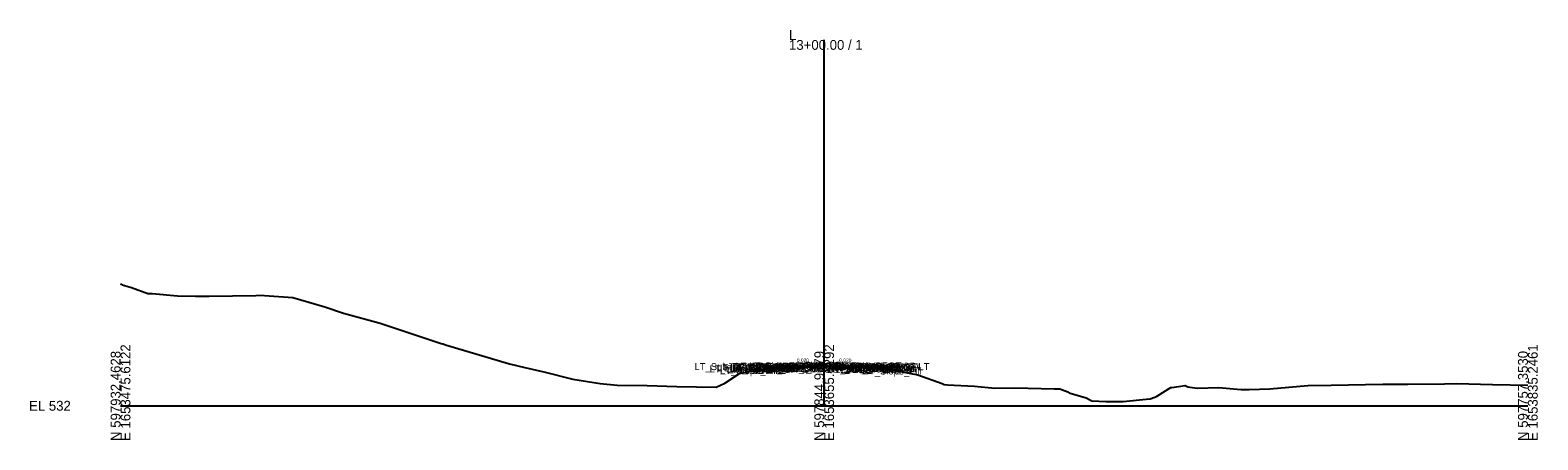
# Model space of a CAD drawing. Extents: x -26 to 403, y -10 to 6021.
# Drawn here: x -25.7 to 402.8, y 1490.3 to 1606.9 of the extents above; entities that cross this region are included whole.
import ezdxf

# ---------------------------------------------------------------- set-up
doc = ezdxf.new("R2010")
doc.units = 0
for name, color, linetype in [('Default', 7, 'Continuous'), ('Exist Cross Section Cell', 7, 'Continuous'), ('Exist XS Ground Line', 7, 'Continuous'), ('Prop CMT Pvmt Course 1', 7, 'Continuous'), ('Prop CMT Pvmt Course 1 Wedge', 7, 'Continuous'), ('Prop CMT Pvmt Course 2', 7, 'Continuous'), ('Prop CMT Pvmt Course 2 Wedge', 7, 'Continuous'), ('Prop CMT Pvmt Course 3', 7, 'Continuous'), ('Prop CMT Pvmt Course 3 Wedge', 7, 'Continuous'), ('Prop CMT Pvmt Surface', 7, 'Continuous'), ('Prop CMT Pvmt Surface Shoulder', 7, 'Continuous'), ('Prop CMT Pvmt Wedge Surface 1', 7, 'Continuous'), ('Prop CMT Pvmt Wedge Surface 2', 7, 'Continuous'), ('Prop CMT Pvmt Wedge Surface 3', 7, 'Continuous'), ('Prop CMT Shld Paved Course 1', 7, 'Continuous'), ('Prop CMT Shld Paved Course 2', 7, 'Continuous'), ('Prop CMT Shld Paved Course 3', 7, 'Continuous'), ('Prop CMT Slope Grass', 7, 'Continuous'), ('Prop CMT Subgrade Earthwork', 7, 'Continuous'), ('Prop XS Earthwork Shape', 7, 'Continuous'), ('Prop XS SE Text', 7, 'Continuous'), ('Prop XS Side Slope Text', 7, 'Continuous')]:
    doc.layers.add(name, color=color, linetype=linetype)

msp = doc.modelspace()

# ---------------------------------------------------------------- linework, layer by layer
at = {"layer": 'Exist Cross Section Cell'}
for p, q in [((200, 1500), (200, 1604.06)), ((0, 1500), (200, 1500)), ((200, 1500), (400, 1500))]:
    msp.add_line(p, q, dxfattribs=at)
at = {"layer": 'Exist XS Ground Line'}
msp.add_lwpolyline([(0, 1534.69), (0.19, 1534.58), (0.5, 1534.44), (3.08, 1533.62), (7.78, 1531.98), (9, 1531.93), (16.22, 1531.26), (21.33, 1531.19), (25.23, 1531.22), (38.45, 1531.42), (40.38, 1531.43), (40.92, 1531.39), (48.94, 1530.79), (58.11, 1528.12), (63.4, 1526.38), (73.77, 1523.51), (91.1, 1517.76), (91.5, 1517.63), (91.67, 1517.58), (92.34, 1517.38), (110.56, 1511.93), (114.94, 1510.89), (120.29, 1509.62), (128.56, 1507.56), (136.35, 1506.34), (141.2, 1505.87), (149.69, 1505.77), (158.1, 1505.49), (169.29, 1505.28), (171.71, 1506.47), (175.9, 1509.17), (180.56, 1510.18), (181.65, 1510.32), (182.55, 1510.41), (188.16, 1510.74), (192.17, 1510.87), (200, 1511.2), (200.17, 1511.2), (208.64, 1510.99), (211.99, 1510.91), (216.34, 1510.44), (221.73, 1509.73), (226.64, 1508.83), (233.53, 1506.32), (234.14, 1506.03), (235.04, 1505.99), (242.71, 1505.59), (248.53, 1505.05), (254.21, 1505.07), (265.42, 1504.79), (266.96, 1504.78), (269.22, 1503.95), (269.9, 1503.6), (274.43, 1502.26), (276.1, 1501.45), (280.09, 1501.26), (284.96, 1501.24), (291.5, 1501.89), (292.67, 1501.99), (292.92, 1502.03), (294.47, 1502.6), (298.05, 1504.9), (298.53, 1505.19), (298.56, 1505.2), (298.7, 1505.21), (298.8, 1505.22), (302.59, 1505.73), (303.33, 1505.37), (306, 1505.05), (312.15, 1505.25), (316.3, 1504.87), (318.5, 1504.68), (320.82, 1504.62), (326.67, 1504.86), (337.51, 1505.75), (344.13, 1505.84), (358.75, 1506.12), (360.75, 1506.18), (365.91, 1506.19), (376.3, 1506.24), (379.8, 1506.37), (389.93, 1506.1), (400, 1505.87)], dxfattribs=at)
at = {"layer": 'Prop CMT Pvmt Course 1'}
for points in [[(200, 1511.57), (188, 1511.33)], [(188, 1511.33), (188, 1511.12)], [(188, 1511.12), (188.16, 1511.12)], [(188.16, 1511.12), (200, 1511.36)], [(188.16, 1511.12), (188.16, 1511.12)], [(200, 1511.36), (200, 1511.57)], [(200, 1511.57), (212, 1511.33)], [(200, 1511.36), (200, 1511.57)], [(200, 1511.36), (200, 1511.36), (200, 1511.36)], [(211.99, 1511.12), (200, 1511.36)], [(200, 1511.36), (200, 1511.36), (200, 1511.36)], [(212, 1511.12), (211.99, 1511.12)], [(211.99, 1511.12), (211.99, 1511.12)], [(212, 1511.33), (212, 1511.12)]]:
    msp.add_lwpolyline(points, dxfattribs=at)
at = {"layer": 'Prop CMT Pvmt Course 1 Wedge'}
for points in [[(188.16, 1511.12), (192.17, 1511.2), (200, 1511.36)], [(200, 1511.24), (192.17, 1511.08), (188.16, 1511)], [(188.16, 1511), (188.16, 1511.12)], [(200, 1511.36), (200, 1511.24)], [(200, 1511.36), (200.17, 1511.36), (208.64, 1511.19), (211.99, 1511.12)], [(200, 1511.24), (200, 1511.36)], [(211.99, 1511), (208.64, 1511.06), (200.17, 1511.23), (200, 1511.24)], [(211.99, 1511.12), (211.99, 1511), (211.99, 1511)]]:
    msp.add_lwpolyline(points, dxfattribs=at)
at = {"layer": 'Prop CMT Pvmt Course 2'}
for points in [[(188.16, 1511.12), (188, 1511.12)], [(188, 1511.12), (188, 1510.91)], [(188, 1510.91), (188.16, 1510.92)], [(188.16, 1510.92), (188.16, 1511.12)], [(211.99, 1510.91), (211.99, 1511.12)], [(211.99, 1511.12), (212, 1511.12)], [(212, 1510.91), (211.99, 1510.91)], [(212, 1511.12), (212, 1510.91)]]:
    msp.add_lwpolyline(points, dxfattribs=at)
at = {"layer": 'Prop CMT Pvmt Course 2 Wedge'}
for points in [[(188.16, 1511.12), (192.17, 1511.2), (200, 1511.36)], [(200, 1511.2), (197.95, 1511.11), (192.17, 1511), (188.16, 1510.92)], [(188.16, 1510.92), (188.16, 1511.12)], [(200, 1511.36), (200, 1511.2)], [(200, 1511.36), (200.17, 1511.36), (208.64, 1511.19), (211.99, 1511.12)], [(200, 1511.2), (200, 1511.36)], [(211.99, 1510.91), (211.17, 1510.93), (208.64, 1510.99), (200.17, 1511.2), (200, 1511.2)], [(211.99, 1511.12), (211.99, 1510.91), (211.99, 1510.91)]]:
    msp.add_lwpolyline(points, dxfattribs=at)
at = {"layer": 'Prop CMT Pvmt Course 3'}
for points in [[(188.16, 1510.92), (188, 1510.91)], [(188, 1510.91), (188, 1510.58)], [(188, 1510.58), (188.16, 1510.58)], [(188.16, 1510.58), (188.16, 1510.92)], [(211.99, 1510.91), (212, 1510.91)], [(211.99, 1510.58), (211.99, 1510.91)], [(212, 1510.58), (211.99, 1510.58)], [(212, 1510.91), (212, 1510.58)]]:
    msp.add_lwpolyline(points, dxfattribs=at)
at = {"layer": 'Prop CMT Pvmt Course 3 Wedge'}
for points in [[(188.16, 1510.92), (192.17, 1511), (197.95, 1511.11)], [(197.95, 1511.11), (192.17, 1510.87), (188.16, 1510.74)], [(188.16, 1510.74), (188.16, 1510.92)], [(211.99, 1510.91), (211.17, 1510.93)], [(211.17, 1510.93), (211.99, 1510.91)], [(211.99, 1510.91), (211.99, 1510.91), (211.99, 1510.91)]]:
    msp.add_lwpolyline(points, dxfattribs=at)
at = {"layer": 'Prop CMT Pvmt Surface'}
for points in [[(200, 1511.57), (188, 1511.33)], [(200, 1511.57), (212, 1511.33)]]:
    msp.add_lwpolyline(points, dxfattribs=at)
at = {"layer": 'Prop CMT Pvmt Surface Shoulder'}
for points in [[(188, 1511.33), (184, 1511.25)], [(212, 1511.33), (216, 1511.25)]]:
    msp.add_lwpolyline(points, dxfattribs=at)
at = {"layer": 'Prop CMT Pvmt Wedge Surface 1'}
for points in [[(188, 1511.12), (188, 1511.33)], [(188.16, 1511.12), (188, 1511.12)], [(200, 1511.36), (188.16, 1511.12)], [(188.16, 1511.12), (188.16, 1511.12)], [(200, 1511.57), (200, 1511.36), (200, 1511.36), (200, 1511.36)], [(200, 1511.57), (200, 1511.36), (200, 1511.36), (200, 1511.36)], [(200, 1511.36), (211.99, 1511.12)], [(211.99, 1511.12), (211.99, 1511.12)], [(211.99, 1511.12), (212, 1511.12)], [(212, 1511.12), (212, 1511.33)]]:
    msp.add_lwpolyline(points, dxfattribs=at)
at = {"layer": 'Prop CMT Pvmt Wedge Surface 2'}
for points in [[(200, 1511.36), (188, 1511.12)], [(188, 1511.12), (188, 1511.33)], [(200, 1511.57), (200, 1511.36)], [(200, 1511.57), (200, 1511.36)], [(200, 1511.36), (212, 1511.12)], [(212, 1511.12), (212, 1511.33)]]:
    msp.add_lwpolyline(points, dxfattribs=at)
at = {"layer": 'Prop CMT Pvmt Wedge Surface 3'}
for points in [[(188, 1510.91), (188, 1511.33)], [(200, 1511.15), (188, 1510.91)], [(200, 1511.57), (200, 1511.15)], [(200, 1511.57), (200, 1511.15)], [(200, 1511.15), (212, 1510.91)], [(212, 1510.91), (212, 1511.33)]]:
    msp.add_lwpolyline(points, dxfattribs=at)
at = {"layer": 'Prop CMT Shld Paved Course 1'}
for points in [[(188, 1511.33), (184, 1511.25), (183.79, 1511.04)], [(183.79, 1511.04), (188, 1511.12)], [(188, 1511.12), (188, 1511.33)], [(212, 1511.33), (216, 1511.25), (216.21, 1511.04)], [(212, 1511.12), (212, 1511.33)], [(216.21, 1511.04), (212, 1511.12)]]:
    msp.add_lwpolyline(points, dxfattribs=at)
at = {"layer": 'Prop CMT Shld Paved Course 2'}
for points in [[(188, 1511.12), (183.79, 1511.04), (183.57, 1510.82)], [(183.57, 1510.82), (188, 1510.91)], [(188, 1510.91), (188, 1511.12)], [(212, 1511.12), (216.21, 1511.04), (216.43, 1510.82)], [(212, 1510.91), (212, 1511.12)], [(216.43, 1510.82), (212, 1510.91)]]:
    msp.add_lwpolyline(points, dxfattribs=at)
at = {"layer": 'Prop CMT Shld Paved Course 3'}
for points in [[(183.57, 1510.82), (183.23, 1510.48)], [(183.23, 1510.48), (188, 1510.58)], [(188, 1510.91), (183.57, 1510.82)], [(183.57, 1510.82), (183.57, 1510.82)], [(188, 1510.58), (188, 1510.91)], [(212, 1510.91), (216.43, 1510.82)], [(212, 1510.58), (212, 1510.91)], [(216.77, 1510.48), (212, 1510.58)], [(216.43, 1510.82), (216.43, 1510.82)], [(216.43, 1510.82), (216.77, 1510.48)]]:
    msp.add_lwpolyline(points, dxfattribs=at)
at = {"layer": 'Prop CMT Slope Grass'}
for points in [[(184, 1511.25), (182, 1511.09), (179.88, 1510.03)], [(216, 1511.25), (218, 1511.09), (220.36, 1509.91)]]:
    msp.add_lwpolyline(points, dxfattribs=at)
at = {"layer": 'Prop CMT Subgrade Earthwork'}
for points in [[(183.23, 1510.48), (182.58, 1511.14)], [(188, 1510.58), (183.23, 1510.48)], [(188.16, 1510.58), (188, 1510.58)], [(188.16, 1510.58), (188.17, 1510.74)], [(211.99, 1510.58), (211.98, 1510.91)], [(211.99, 1510.58), (212, 1510.58)], [(212, 1510.58), (216.77, 1510.48)], [(216.77, 1510.48), (217.42, 1511.14)]]:
    msp.add_lwpolyline(points, dxfattribs=at)
at = {"layer": 'Prop XS Earthwork Shape'}
for points in [[(183.23, 1510.48), (182.58, 1511.14), (182, 1511.09), (179.88, 1510.03), (180.56, 1510.18), (181.65, 1510.32), (182.55, 1510.41), (184.19, 1510.5)], [(183.23, 1510.48), (182.58, 1511.14), (182, 1511.09), (179.88, 1510.03), (180.56, 1510.18), (181.65, 1510.32), (182.55, 1510.41), (184.19, 1510.5)], [(183.23, 1510.48), (182.58, 1511.14), (182, 1511.09), (179.88, 1510.03), (180.56, 1510.18), (181.65, 1510.32), (182.55, 1510.41), (184.19, 1510.5)], [(184, 1511.25), (182.58, 1511.14), (183.23, 1510.48), (184.19, 1510.5), (188.16, 1510.74), (188.17, 1510.74), (192.17, 1510.87), (200, 1511.2), (200.17, 1511.2), (208.64, 1510.99), (211.98, 1510.91), (211.99, 1510.91), (215.73, 1510.5), (216.77, 1510.48), (217.42, 1511.14), (216, 1511.25), (212, 1511.33), (212, 1511.12), (200, 1511.36), (188.16, 1511.12), (188, 1511.12), (188, 1511.33)], [(184, 1511.25), (182.58, 1511.14), (183.23, 1510.48), (184.19, 1510.5), (188.16, 1510.74), (188.17, 1510.74), (192.17, 1510.87), (200, 1511.2), (200.17, 1511.2), (208.64, 1510.99), (211.98, 1510.91), (211.99, 1510.91), (215.73, 1510.5), (216.77, 1510.48), (217.42, 1511.14), (216, 1511.25), (212, 1511.33), (212, 1511.12), (200, 1511.36), (188.16, 1511.12), (188, 1511.12), (188, 1511.33)], [(184, 1511.25), (182.58, 1511.14), (183.23, 1510.48), (184.19, 1510.5), (188.16, 1510.74), (188.17, 1510.74), (192.17, 1510.87), (200, 1511.2), (200.17, 1511.2), (208.64, 1510.99), (211.98, 1510.91), (211.99, 1510.91), (215.73, 1510.5), (216.77, 1510.48), (217.42, 1511.14), (216, 1511.25), (212, 1511.33), (212, 1511.12), (200, 1511.36), (188.16, 1511.12), (188, 1511.12), (188, 1511.33)], [(188.16, 1510.58), (188.17, 1510.74), (188.16, 1510.74), (184.19, 1510.5), (188, 1510.58)], [(188.16, 1510.58), (188.17, 1510.74), (188.16, 1510.74), (184.19, 1510.5), (188, 1510.58)], [(188.16, 1510.58), (188.17, 1510.74), (188.16, 1510.74), (184.19, 1510.5), (188, 1510.58)], [(211.99, 1510.58), (215.73, 1510.5), (211.99, 1510.91), (211.98, 1510.91)], [(211.99, 1510.58), (215.73, 1510.5), (211.99, 1510.91), (211.98, 1510.91)], [(211.99, 1510.58), (215.73, 1510.5), (211.99, 1510.91), (211.98, 1510.91)], [(216.77, 1510.48), (217.42, 1511.14), (218, 1511.09), (220.36, 1509.91), (216.34, 1510.44), (215.73, 1510.5)], [(216.77, 1510.48), (217.42, 1511.14), (218, 1511.09), (220.36, 1509.91), (216.34, 1510.44), (215.73, 1510.5)], [(216.77, 1510.48), (217.42, 1511.14), (218, 1511.09), (220.36, 1509.91), (216.34, 1510.44), (215.73, 1510.5)]]:
    msp.add_lwpolyline(points, close=True, dxfattribs=at)

# ---------------------------------------------------------------- texts
at = {"layer": 'Default'}
for s, height, p in [('LT_Sub_Trench_Out_DLT', 2, (163.15, 1510.14)), ('LT_Sub_Trench_Out', 2, (167.44, 1509.48)), ('LT_PS3_Shelf_Out', 2, (169.56, 1509.82)), ('LT_Slope_Fill', 2, (170.4, 1509.03)), ('LT_GS_OS_CTL', 2, (171.37, 1510.09)), ('LT_PV_Sub_Tie_Out', 2, (173.12, 1509.74)), ('LT_PS3_OEOP', 2, (173.81, 1509.82)), ('LT_PS2_OEOP', 2, (174.02, 1510.04)), ('LT_PS1_OEOP', 2, (174.8, 1510.25)), ('LT_PV_OEEOP_EG', 2, (175.7, 1509.74)), ('LT_Sub_OEEOP', 2, (177.37, 1509.58)), ('LT_PV2_OEEOP', 2, (177.46, 1510.12)), ('LT_PV3_OEEOP', 2, (177.46, 1509.92)), ('LT_PV1_OEEOP', 2, (178.03, 1510.12)), ('LT_Sub_OEOT', 2, (178.08, 1509.58)), ('LT_PV2_OEOT', 2, (178.17, 1510.12)), ('LT_PV3_OEOT', 2, (178.17, 1509.91)), ('LT_PV1_OEOT', 2, (178.74, 1510.33)), ('LT_PV_EG_TestPt', 2, (180.49, 1509.95)), ('RT_PV_IEEOP_EG', 2, (188.14, 1510.2)), ('LT_PV_IEEOP_EG', 2, (188.19, 1510.2)), ('RT_PV2_IEEOP', 2, (189.91, 1510.36)), ('RT_PV3_IEEOP', 2, (189.91, 1510.15)), ('LT_PV2_IEEOP', 2, (189.95, 1510.36)), ('LT_PV3_IEEOP', 2, (189.95, 1510.15)), ('RT_PV1_IEEOP', 2, (190.47, 1510.36)), ('LT_PV1_IEEOP', 2, (190.52, 1510.36)), ('RT_PV_EG_TestPt', 2, (192.36, 1510.06)), ('PV2_PGL', 2, (193.91, 1510.36)), ('PV3_PGL', 2, (193.91, 1510.15)), ('PV1_PGL', 2, (194.47, 1510.57)), ('RT_PV_Sub_Tie_Out', 2, (196.87, 1509.91)), ('RT_Sub_Trench_Out_DLT', 2, (197.94, 1510.14)), ('RT_PV_OEEOP_EG', 2, (199.49, 1509.91)), ('RT_Sub_Trench_Out', 2, (200.92, 1509.48)), ('RT_Sub_OEEOP', 2, (201.16, 1509.58)), ('RT_PV2_OEEOP', 2, (201.25, 1510.12)), ('RT_PV3_OEEOP', 2, (201.25, 1509.91)), ('RT_PV1_OEEOP', 2, (201.82, 1510.12)), ('RT_Sub_OEOT', 2, (202.03, 1509.58)), ('RT_PV2_OEOT', 2, (202.13, 1510.12)), ('RT_PV3_OEOT', 2, (202.13, 1509.91)), ('RT_PS3_Shelf_Out', 2, (202.36, 1509.82)), ('RT_PV1_OEOT', 2, (202.69, 1510.33)), ('RT_PS2_OEOP', 2, (206.4, 1510.04)), ('RT_PS3_OEOP', 2, (206.61, 1509.82)), ('RT_PS1_OEOP', 2, (206.76, 1510.25)), ('RT_GS_OS_CTL', 2, (207.32, 1510.09)), ('RT_Slope_Fill', 2, (210.83, 1508.91)), ('-', 0.0001, (0, 1500))]:
    msp.add_text(s, height=height, dxfattribs=at).set_placement(p)
at = {"layer": 'Exist Cross Section Cell'}
for s, p in [('13+00.00 / 1', (190, 1601.26)), ('L', (190, 1604.06)), ('EL 532', (-26, 1498.6))]:
    msp.add_text(s, height=2.8, dxfattribs=at).set_placement(p)
for s, p in [('E 1653475.6122', (2.8, 1490)), ('E 1653655.4292', (202.8, 1490)), ('E 1653835.2461', (402.8, 1490)), ('N 597932.4628', (0, 1490)), ('N 597844.9079', (200, 1490)), ('N 597757.3530', (400, 1490))]:
    msp.add_text(s, height=2.8, rotation=90, dxfattribs=at).set_placement(p)
at = {"layer": 'Prop XS SE Text'}
for rotation, p in [(1.1458, (192.23, 1512.41)), (358.8542, (204.27, 1512.48))]:
    msp.add_text('0.020', height=1, rotation=rotation, dxfattribs=at).set_placement(p)
at = {"layer": 'Prop XS Side Slope Text'}
for rotation, p in [(26.5651, (179.9, 1510.88)), (333.4349, (218.81, 1511.52))]:
    msp.add_text('2:1', height=1, rotation=rotation, dxfattribs=at).set_placement(p)

doc.saveas('drawing.dxf')
